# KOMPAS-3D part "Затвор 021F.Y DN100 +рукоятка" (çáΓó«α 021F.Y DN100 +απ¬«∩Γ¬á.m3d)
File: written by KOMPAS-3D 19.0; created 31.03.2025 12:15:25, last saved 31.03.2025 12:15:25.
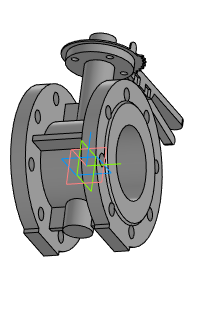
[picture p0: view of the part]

Document properties: Автор: Евгений; Полное имя файла: Затвор 021F.Y DN100 +рукоятка.a3d

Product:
- Part/product: Затвор 021F.Y DN100 +рукоятка
    Масса: 23.4203

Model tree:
1. Операция без истории:1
